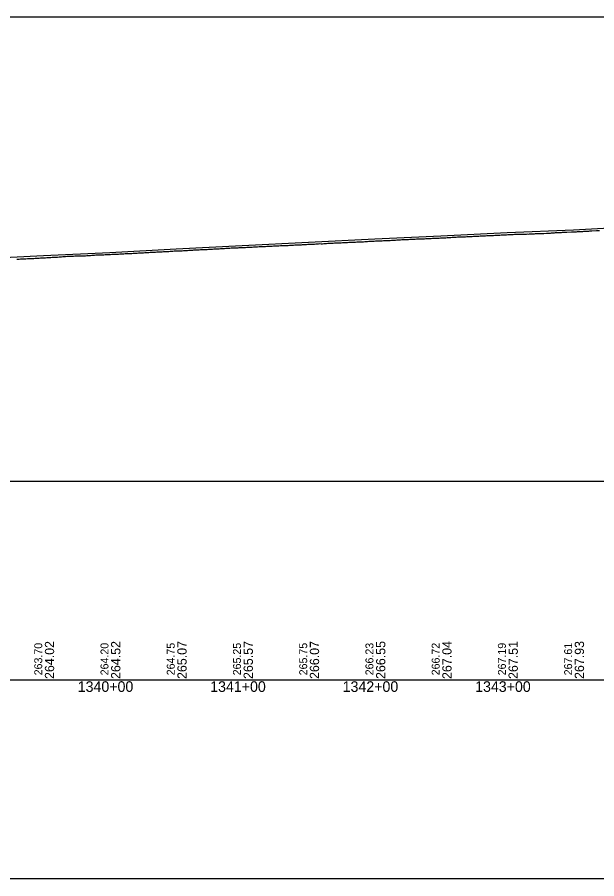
# Model space of a CAD drawing. Extents: x 2898 to 49495, y -15038 to -13538.
# Drawn here: x 23383 to 23821, y -15038 to -14388 of the extents above; entities that cross this region are included whole.
import ezdxf

# ---------------------------------------------------------------- set-up
doc = ezdxf.new("R2010")
doc.units = 0
for name, color, linetype in [('RD_DDB_Profile_EX', 7, 'Continuous'), ('RD_DDB_Profile_PR', 7, 'Continuous'), ('RD_DDB_StaTX', 7, 'Continuous'), ('RD_DDB_StripGrade', 7, 'Continuous'), ('RD_GPK_Profile_Cell', 7, 'Continuous'), ('RD_SHT_ShtClip', 7, 'Continuous')]:
    doc.layers.add(name, color=color, linetype=linetype)

msp = doc.modelspace()

# ---------------------------------------------------------------- linework, layer by layer
at = {"layer": 'RD_DDB_Profile_EX'}
for points in [[(23649.94, -14557.43), (23650.94, -14557.38), (23651.94, -14557.35), (23652.94, -14557.34), (23653.94, -14557.29), (23654.94, -14557.24), (23655.94, -14557.17), (23656.94, -14557.12), (23657.94, -14557.14), (23658.94, -14557.09), (23659.94, -14557.01), (23660.94, -14556.96), (23661.94, -14556.94), (23662.94, -14556.93), (23663.94, -14556.88), (23664.93, -14556.88), (23665.94, -14556.77), (23666.94, -14556.71), (23667.93, -14556.61), (23668.93, -14556.56), (23669.94, -14556.46), (23670.93, -14556.36), (23671.94, -14556.36), (23672.94, -14556.31), (23673.93, -14556.27), (23674.94, -14556.26), (23675.93, -14556.17), (23676.94, -14556.2), (23677.94, -14556.1), (23678.93, -14556.19), (23679.93, -14556.01), (23680.93, -14555.93), (23681.93, -14555.89), (23682.94, -14555.89), (23683.94, -14555.84), (23684.93, -14555.78), (23685.93, -14555.78), (23686.93, -14555.73), (23687.94, -14555.72), (23688.94, -14555.59), (23689.93, -14555.58), (23690.93, -14555.56), (23691.93, -14555.46), (23692.93, -14555.43), (23693.94, -14555.39), (23694.94, -14555.36), (23695.93, -14555.37), (23696.93, -14555.22), (23697.93, -14555.22), (23698.94, -14555.19), (23699.93, -14555.11), (23700.93, -14555.08), (23701.93, -14555.03), (23702.93, -14554.91), (23703.93, -14554.86), (23704.94, -14554.84), (23705.93, -14554.92), (23706.93, -14554.84), (23707.93, -14554.76), (23708.94, -14554.6), (23709.93, -14554.53), (23710.93, -14554.53), (23711.93, -14554.49), (23712.94, -14554.4), (23713.93, -14554.38), (23714.94, -14554.29), (23715.93, -14554.27), (23716.93, -14554.27), (23717.93, -14554.22), (23718.93, -14554.18), (23719.94, -14554.11), (23720.93, -14554.08), (23721.94, -14554.04), (23722.94, -14554), (23723.94, -14553.99), (23724.93, -14553.91), (23725.39, -14553.87), (23725.94, -14553.81), (23726.93, -14553.79), (23727.94, -14553.74), (23728.93, -14553.64), (23729.94, -14553.63), (23730.94, -14553.63), (23731.94, -14553.54), (23732.93, -14553.47), (23733.35, -14553.45), (23733.94, -14553.45), (23734.93, -14553.4), (23735.94, -14553.33), (23736.94, -14553.36), (23737.94, -14553.23), (23738.94, -14553.2), (23739.93, -14553.16), (23740.94, -14553.09), (23741.31, -14553.09), (23741.93, -14553.09), (23742.94, -14553.02), (23743.94, -14552.98), (23744.94, -14552.93), (23745.94, -14552.88), (23746.93, -14552.84)], [(23746.93, -14552.84), (23747.93, -14552.79), (23748.94, -14552.74), (23749.27, -14552.71), (23749.93, -14552.65), (23750.94, -14552.67), (23751.93, -14552.62), (23752.93, -14552.57), (23753.93, -14552.44), (23754.93, -14552.43), (23755.94, -14552.35), (23757.22, -14552.34), (23757.94, -14552.32), (23758.94, -14552.22), (23759.94, -14552.2), (23760.94, -14552.18), (23761.94, -14552.17), (23762.93, -14552.1), (23763.94, -14552.08), (23765.18, -14552.17), (23765.83, -14552.1), (23766.4, -14552.08), (23767.15, -14552.08), (23767.9, -14552.01), (23768.65, -14551.97), (23769.41, -14552.01), (23770.17, -14551.97), (23770.93, -14551.89), (23771.69, -14551.85), (23772.45, -14551.82), (23773.21, -14551.78), (23773.99, -14551.78), (23774.77, -14551.74), (23775.54, -14551.74), (23776.31, -14551.7), (23777.09, -14551.66), (23781.1, -14551.52), (23783.08, -14551.45), (23783.82, -14551.38), (23784.56, -14551.3), (23785.3, -14551.3), (23786.05, -14551.34), (23786.79, -14551.22), (23787.56, -14551.15), (23788.32, -14551.11), (23789.07, -14551.11), (23789.83, -14550.99), (23790.6, -14550.95), (23791.36, -14550.99), (23792.13, -14550.91), (23792.91, -14550.84), (23793.68, -14550.8), (23794.46, -14550.76), (23795.22, -14550.72), (23795.99, -14550.64), (23797.01, -14550.65), (23797.52, -14550.65), (23798.29, -14550.61), (23801.91, -14550.41), (23802.67, -14550.41), (23803.45, -14550.41), (23804.23, -14550.34), (23805, -14550.34), (23805.78, -14550.26), (23806.55, -14550.18), (23807.32, -14550.11), (23808.1, -14550.07), (23808.87, -14550.07), (23809.64, -14550.07), (23810.41, -14550.03), (23811.18, -14549.95), (23811.95, -14549.99), (23812.93, -14549.94), (23813.49, -14549.91), (23814.26, -14549.91), (23815.03, -14549.8), (23815.8, -14549.68), (23816.57, -14549.64), (23817.34, -14549.64), (23820.88, -14549.45), (23822.95, -14549.34)], [(23550.95, -14562.32), (23551.94, -14562.31), (23552.94, -14562.21), (23553.94, -14562.17), (23554.94, -14562.16), (23555.94, -14562.08), (23556.94, -14562.04), (23557.94, -14561.99), (23558.28, -14561.98), (23558.95, -14561.94), (23559.94, -14561.85), (23560.94, -14561.83), (23561.94, -14561.77), (23562.94, -14561.75), (23563.94, -14561.66), (23564.94, -14561.62), (23566.24, -14561.52), (23566.94, -14561.48), (23567.94, -14561.47), (23568.94, -14561.42), (23569.94, -14561.41), (23570.95, -14561.39), (23571.94, -14561.29), (23572.94, -14561.25), (23574.2, -14561.22), (23574.94, -14561.19), (23575.94, -14561.09), (23576.94, -14561.03), (23577.94, -14561.04), (23578.94, -14560.95), (23579.94, -14560.88), (23580.95, -14560.88), (23582.16, -14560.78), (23582.95, -14560.73), (23583.94, -14560.69), (23584.94, -14560.68), (23585.94, -14560.61), (23586.95, -14560.63), (23587.94, -14560.63), (23588.94, -14560.4), (23590.11, -14560.42), (23590.95, -14560.38), (23591.94, -14560.34), (23592.95, -14560.28), (23593.94, -14560.19), (23594.94, -14560.16), (23595.95, -14560.13), (23596.95, -14560.14), (23598.07, -14560.09), (23598.94, -14560.01), (23599.94, -14559.99), (23600.94, -14559.93), (23601.95, -14559.81), (23602.94, -14559.72), (23603.94, -14559.7), (23604.94, -14559.66), (23606.03, -14559.69), (23606.94, -14559.69), (23607.95, -14559.59), (23608.94, -14559.49), (23609.94, -14559.43), (23610.95, -14559.35), (23611.95, -14559.3), (23612.94, -14559.39), (23613.99, -14559.47), (23614.94, -14559.23), (23615.94, -14559.14), (23616.95, -14559.06), (23617.94, -14559), (23618.94, -14559.01), (23619.94, -14558.97), (23620.95, -14558.88), (23621.94, -14558.83), (23622.94, -14558.72), (23623.94, -14558.66), (23624.95, -14558.67), (23625.94, -14558.6), (23626.94, -14558.58), (23627.94, -14558.62), (23628.95, -14558.52), (23629.94, -14558.45), (23630.95, -14558.4), (23631.94, -14558.41), (23632.94, -14558.37), (23633.94, -14558.28), (23634.94, -14558.25), (23635.94, -14558.13), (23636.94, -14558.12), (23637.94, -14558.11), (23638.94, -14558.05), (23639.94, -14557.91), (23640.95, -14557.91), (23641.94, -14557.81), (23642.94, -14557.81), (23643.94, -14557.81), (23644.94, -14557.8), (23645.94, -14557.66), (23646.94, -14557.65), (23647.94, -14557.55), (23648.94, -14557.5), (23649.94, -14557.43)], [(23453.94, -14567.5), (23454.95, -14567.27), (23455.95, -14567.24), (23456.94, -14567.25), (23457.95, -14567.2), (23458.95, -14567.19), (23459.95, -14567.27), (23460.94, -14567.09), (23461.94, -14566.97), (23462.94, -14566.96), (23463.95, -14566.92), (23464.95, -14566.82), (23465.94, -14566.82), (23466.95, -14566.82), (23467.94, -14566.71), (23468.95, -14566.66), (23469.95, -14566.61), (23470.95, -14566.55), (23471.95, -14566.46), (23472.94, -14566.44), (23473.94, -14566.39), (23474.94, -14566.3), (23475.95, -14566.27), (23476.95, -14566.26), (23477.94, -14566.17), (23478.94, -14566.14), (23479.95, -14566.05), (23480.95, -14565.99), (23481.94, -14565.98), (23482.95, -14565.91), (23483.94, -14565.83), (23484.94, -14565.78), (23485.95, -14565.75), (23486.94, -14565.66), (23487.94, -14565.62), (23488.95, -14565.54), (23489.94, -14565.47), (23490.94, -14565.42), (23491.95, -14565.39), (23492.94, -14565.34), (23493.94, -14565.3), (23494.95, -14565.25), (23495.94, -14565.11), (23496.94, -14565.09), (23497.94, -14565.1), (23498.94, -14565.01), (23499.94, -14565.07), (23500.94, -14564.89), (23501.95, -14564.75), (23502.94, -14564.74), (23503.94, -14564.69), (23504.94, -14564.64), (23505.94, -14564.67), (23506.95, -14564.68), (23507.94, -14564.62), (23508.94, -14564.57), (23509.95, -14564.51), (23510.94, -14564.38), (23511.94, -14564.37), (23512.94, -14564.31), (23513.94, -14564.21), (23514.95, -14564.13), (23515.94, -14564.11), (23516.94, -14564.07), (23517.94, -14564.01), (23518.94, -14563.95), (23519.94, -14563.9), (23520.94, -14563.89), (23521.94, -14563.81), (23522.94, -14563.82), (23523.94, -14563.77), (23524.94, -14563.69), (23525.94, -14563.64), (23526.94, -14563.63), (23527.94, -14563.54), (23528.94, -14563.44), (23529.94, -14563.4), (23530.94, -14563.33), (23531.94, -14563.24), (23532.94, -14563.24), (23533.94, -14563.17), (23534.41, -14563.15), (23534.95, -14563.12), (23535.94, -14563.1), (23536.94, -14563.02), (23537.94, -14562.95), (23538.94, -14562.93), (23539.94, -14562.86), (23540.94, -14562.75), (23541.94, -14562.79), (23542.37, -14562.75), (23542.95, -14562.71), (23543.94, -14562.66), (23544.94, -14562.57), (23545.94, -14562.56), (23546.94, -14562.52), (23547.94, -14562.51), (23548.94, -14562.46), (23549.94, -14562.44), (23550.32, -14562.38), (23550.95, -14562.32)], [(23383.21, -14570.94), (23383.96, -14570.95), (23384.96, -14570.91), (23385.96, -14570.78), (23386.96, -14570.78), (23387.96, -14570.69), (23388.96, -14570.69), (23389.96, -14570.68), (23391.17, -14570.57), (23391.96, -14570.53), (23392.96, -14570.49), (23393.96, -14570.44), (23394.96, -14570.4), (23395.96, -14570.37), (23396.96, -14570.27), (23397.96, -14570.22), (23399.13, -14570.22), (23399.96, -14570.27), (23400.96, -14570.07), (23401.96, -14570.04), (23402.96, -14569.98), (23403.96, -14569.91), (23404.96, -14569.92), (23405.96, -14569.84), (23407.09, -14569.73), (23407.96, -14569.66), (23408.95, -14569.62), (23409.96, -14569.58), (23410.95, -14569.55), (23411.96, -14569.57), (23412.95, -14569.53), (23413.96, -14569.38), (23415.04, -14569.31), (23415.95, -14569.24), (23416.95, -14569.15), (23417.95, -14569.01), (23418.95, -14568.95), (23419.95, -14568.92), (23420.95, -14568.85), (23421.95, -14568.84), (23423, -14568.74), (23423.95, -14568.65), (23424.95, -14568.69), (23425.95, -14568.62), (23426.95, -14568.6), (23427.95, -14568.58), (23428.95, -14568.5), (23429.94, -14568.5), (23430.96, -14568.5), (23431.94, -14568.5), (23432.95, -14568.47), (23433.95, -14568.42), (23434.95, -14568.4), (23435.95, -14568.33), (23436.94, -14568.29), (23437.95, -14568.25), (23438.94, -14568.21), (23439.94, -14568.07), (23440.94, -14567.94), (23441.95, -14567.93), (23442.95, -14567.84), (23443.95, -14567.81), (23444.94, -14567.8), (23445.94, -14567.75), (23446.94, -14567.7), (23447.95, -14567.7), (23448.95, -14567.63), (23449.94, -14567.59), (23450.94, -14567.52), (23451.94, -14567.46), (23452.95, -14567.48), (23453.94, -14567.5)]]:
    msp.add_lwpolyline(points, dxfattribs=at)
at = {"layer": 'RD_DDB_Profile_PR'}
msp.add_lwpolyline([(23353.38, -14570.82), (23403.38, -14568.35), (23453.38, -14565.89), (23503.38, -14563.12), (23553.38, -14560.59), (23603.38, -14558.11), (23653.38, -14555.72), (23703.38, -14553.28), (23753.38, -14550.91), (23803.38, -14548.81), (23853.38, -14546.14), (23903.38, -14543.5), (23953.38, -14540.95), (24003.38, -14538.17), (24053.38, -14535.82), (24103.38, -14533.51), (24153.38, -14530.95), (24203.38, -14528.49), (24253.38, -14526), (24303.38, -14523.38)], dxfattribs=at)
at = {"layer": 'RD_GPK_Profile_Cell'}
msp.add_line((2976.05, -14888.47), (48721.13, -14888.47), dxfattribs=at)
at = {"layer": 'RD_SHT_ShtClip'}
for points in [[(22475.38, -14388.47), (22475.38, -14888.47), (23975.38, -14888.47), (23975.38, -14888.47), (23975.38, -14388.47), (23975.38, -14388.47)], [(22455.38, -14738.47), (23995.38, -14738.47), (23995.38, -15038.47), (22455.38, -15038.47)]]:
    msp.add_lwpolyline(points, close=True, dxfattribs=at)

# ---------------------------------------------------------------- texts
at = {"layer": 'RD_DDB_StaTX'}
for s, p in [('1340+00', (23429.18, -14897.47)), ('1341+00', (23529.18, -14897.47)), ('1342+00', (23629.18, -14897.47)), ('1343+00', (23729.18, -14897.47))]:
    msp.add_text(s, height=8, dxfattribs=at).set_placement(p)
at = {"layer": 'RD_DDB_StripGrade'}
for s, height, p in [('263.70', 6, (23402.38, -14884.98)), ('264.02', 7, (23411.38, -14887.72)), ('264.20', 6, (23452.38, -14884.98)), ('264.52', 7, (23461.38, -14887.72)), ('264.75', 6, (23502.38, -14884.98)), ('265.07', 7, (23511.38, -14887.72)), ('265.25', 6, (23552.38, -14884.98)), ('265.57', 7, (23561.38, -14887.72)), ('265.75', 6, (23602.38, -14884.98)), ('266.07', 7, (23611.38, -14887.72)), ('266.23', 6, (23652.38, -14884.98)), ('266.55', 7, (23661.38, -14887.72)), ('266.72', 6, (23702.38, -14884.98)), ('267.04', 7, (23711.38, -14887.72)), ('267.19', 6, (23752.38, -14884.98)), ('267.51', 7, (23761.38, -14887.72)), ('267.61', 6, (23802.38, -14884.98)), ('267.93', 7, (23811.38, -14887.72))]:
    msp.add_text(s, height=height, rotation=90, dxfattribs=at).set_placement(p)

doc.saveas('drawing.dxf')
